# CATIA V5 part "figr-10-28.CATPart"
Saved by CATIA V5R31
Part number: Part1
Bounding box of the stored display mesh (mm): x -60 to 70, y 0 to 100.393, z 0 to 0
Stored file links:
  D:\PROJECTS\Project 2021\US EDITION\CATIA V5 6R 2021\Resources\Part Files\c10_catia_v5_6r2021_prt\c10_catia_v5_6r2021_prt\figr-10-28.CATPart
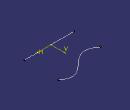
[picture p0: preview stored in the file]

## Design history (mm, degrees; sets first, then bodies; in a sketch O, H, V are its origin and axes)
Body1 (main body)
  Sketch1 on xy-plane, origin (0, 0, 0), H (1, 0, 0), V (0, 1, 0)
    line L1 (-60, 0) -> (70, 0)
    point P1 (-60, 0)
    coincidence: P1 H
    horizontal: L1 H
  Sketch2 on xy-plane, origin (0, 0, 0), H (1, 0, 0), V (0, 1, 0)
    spline S1 through (-60, 70) (-20, 60) (40, 100) (70, 90)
